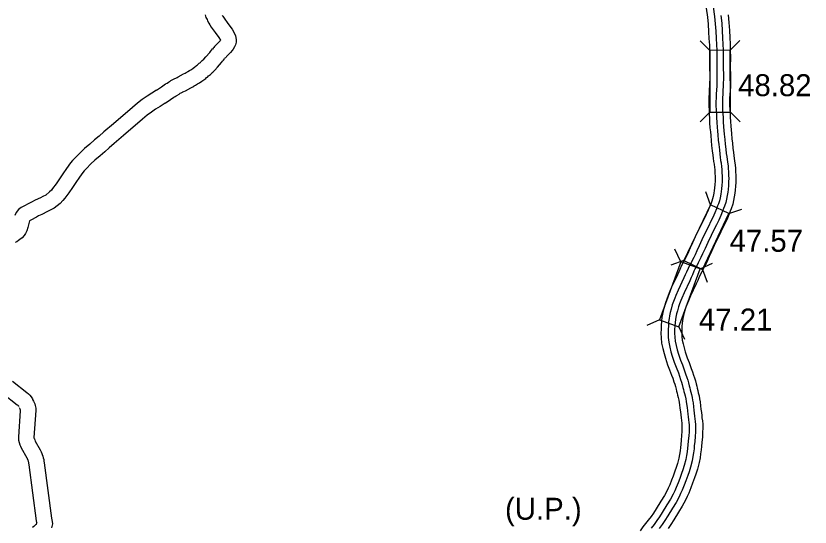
# Model space of a CAD drawing. Extents: x -939622 to -934245, y 1383184 to 1385301.
# Drawn here: x -936375.77 to -936329.92, y 1384824.91 to 1384854.42 of the extents above; entities that cross this region are included whole.
import ezdxf

# ---------------------------------------------------------------- set-up
doc = ezdxf.new("R2010")
doc.units = 0
for name, color, linetype in [('10', 7, 'Continuous'), ('19', 7, 'Continuous'), ('20', 7, 'Continuous'), ('25', 7, 'Continuous')]:
    doc.layers.add(name, color=color, linetype=linetype)

msp = doc.modelspace()

# ---------------------------------------------------------------- linework, layer by layer
at = {"layer": '10'}
for points in [[(-936364.852, 1384854.487), (-936364.799, 1384854.332), (-936364.74, 1384854.21), (-936364.704, 1384854.138), (-936364.639, 1384854.004), (-936364.577, 1384853.909), (-936364.491, 1384853.775), (-936364.262, 1384853.461), (-936364.057, 1384853.166), (-936363.969, 1384853.014), (-936363.984, 1384852.989), (-936364, 1384852.966), (-936364.046, 1384852.913), (-936364.092, 1384852.863), (-936364.136, 1384852.822), (-936364.197, 1384852.762), (-936364.246, 1384852.712), (-936364.305, 1384852.654), (-936364.354, 1384852.595), (-936364.389, 1384852.557), (-936364.429, 1384852.506)], [(-936363.855, 1384854.449), (-936363.822, 1384854.399), (-936363.749, 1384854.285), (-936363.529, 1384853.983), (-936363.296, 1384853.649), (-936363.175, 1384853.439), (-936363.088, 1384853.272), (-936363.053, 1384853.064), (-936363.054, 1384852.908), (-936363.103, 1384852.753), (-936363.149, 1384852.635), (-936363.225, 1384852.504), (-936363.288, 1384852.414), (-936363.375, 1384852.312), (-936363.456, 1384852.225), (-936363.515, 1384852.171), (-936363.557, 1384852.13), (-936363.605, 1384852.079), (-936363.643, 1384852.042), (-936363.678, 1384852), (-936363.704, 1384851.973), (-936363.721, 1384851.951)], [(-936367.65, 1384850.138), (-936367.359, 1384850.327), (-936367.136, 1384850.494), (-936367.041, 1384850.545), (-936366.961, 1384850.6), (-936366.897, 1384850.626), (-936366.885, 1384850.634), (-936366.822, 1384850.684), (-936366.708, 1384850.751), (-936366.628, 1384850.788), (-936366.597, 1384850.804), (-936366.549, 1384850.834), (-936366.459, 1384850.873), (-936366.413, 1384850.897), (-936366.097, 1384851.071), (-936365.991, 1384851.122), (-936365.934, 1384851.156), (-936365.873, 1384851.186), (-936365.838, 1384851.213), (-936365.75, 1384851.262), (-936365.72, 1384851.282), (-936365.679, 1384851.31), (-936365.557, 1384851.392), (-936365.443, 1384851.475), (-936365.376, 1384851.519), (-936365.341, 1384851.552), (-936365.285, 1384851.593), (-936365.265, 1384851.611), (-936365.193, 1384851.682), (-936365.122, 1384851.737), (-936365.09, 1384851.765), (-936365.068, 1384851.785), (-936365.05, 1384851.803), (-936365.019, 1384851.838), (-936364.926, 1384851.926), (-936364.8, 1384852.061), (-936364.586, 1384852.314), (-936364.542, 1384852.366), (-936364.487, 1384852.436), (-936364.423, 1384852.513)], [(-936367.16, 1384849.383), (-936366.843, 1384849.589), (-936366.651, 1384849.733), (-936366.573, 1384849.774), (-936366.529, 1384849.804), (-936366.474, 1384849.827), (-936366.356, 1384849.905), (-936366.312, 1384849.94), (-936366.289, 1384849.953), (-936366.238, 1384849.977), (-936366.157, 1384850.017), (-936366.127, 1384850.036), (-936366.074, 1384850.059), (-936365.99, 1384850.102), (-936365.682, 1384850.272), (-936365.562, 1384850.33), (-936365.506, 1384850.364), (-936365.475, 1384850.379), (-936365.401, 1384850.414), (-936365.341, 1384850.46), (-936365.286, 1384850.49), (-936365.221, 1384850.532), (-936365.174, 1384850.565), (-936365.04, 1384850.654), (-936364.928, 1384850.736), (-936364.812, 1384850.813), (-936364.764, 1384850.859), (-936364.72, 1384850.892), (-936364.651, 1384850.953), (-936364.599, 1384851.004), (-936364.545, 1384851.046), (-936364.488, 1384851.097), (-936364.456, 1384851.125), (-936364.404, 1384851.175), (-936364.37, 1384851.212), (-936364.285, 1384851.294), (-936364.128, 1384851.462), (-936363.895, 1384851.737), (-936363.843, 1384851.799), (-936363.787, 1384851.869), (-936363.727, 1384851.944)], [(-936367.652, 1384850.136), (-936367.927, 1384849.956), (-936368.203, 1384849.788), (-936368.474, 1384849.596), (-936368.752, 1384849.385), (-936369.045, 1384849.138), (-936370.143, 1384848.198), (-936370.691, 1384847.736), (-936370.974, 1384847.486), (-936371.239, 1384847.257), (-936371.509, 1384847.02), (-936371.806, 1384846.758), (-936372.066, 1384846.524), (-936372.346, 1384846.236), (-936372.502, 1384846.071), (-936372.622, 1384845.929), (-936372.842, 1384845.62), (-936373.057, 1384845.307), (-936373.255, 1384845.019), (-936373.455, 1384844.73), (-936373.652, 1384844.451), (-936373.724, 1384844.367), (-936373.829, 1384844.259), (-936374.054, 1384844.081), (-936374.216, 1384843.997), (-936374.354, 1384843.925), (-936374.661, 1384843.775), (-936374.878, 1384843.676), (-936375.029, 1384843.59), (-936375.32, 1384843.431), (-936375.476, 1384843.357), (-936375.624, 1384843.243), (-936375.764, 1384843.071), (-936375.828, 1384842.904)], [(-936367.158, 1384849.384), (-936367.446, 1384849.195), (-936367.709, 1384849.035), (-936367.941, 1384848.871), (-936368.189, 1384848.682), (-936368.462, 1384848.452), (-936369.56, 1384847.512), (-936370.103, 1384847.055), (-936370.381, 1384846.809), (-936370.647, 1384846.579), (-936370.914, 1384846.345), (-936371.207, 1384846.087), (-936371.442, 1384845.875), (-936371.697, 1384845.613), (-936371.83, 1384845.472), (-936371.909, 1384845.378), (-936372.104, 1384845.104), (-936372.316, 1384844.797), (-936372.514, 1384844.508), (-936372.718, 1384844.214), (-936372.941, 1384843.897), (-936373.058, 1384843.762), (-936373.223, 1384843.59), (-936373.565, 1384843.32), (-936373.801, 1384843.199), (-936373.948, 1384843.122), (-936374.276, 1384842.961), (-936374.469, 1384842.873), (-936374.591, 1384842.804), (-936374.911, 1384842.629), (-936374.98, 1384842.596), (-936375.092, 1384842.198), (-936375.145, 1384842.012), (-936375.21, 1384841.856), (-936375.304, 1384841.736), (-936375.418, 1384841.604), (-936375.544, 1384841.504), (-936375.63, 1384841.448), (-936375.723, 1384841.385), (-936375.824, 1384841.342)], [(-936375.975, 1384833.337), (-936375.145, 1384832.682), (-936375.037, 1384832.601), (-936374.97, 1384832.52), (-936374.901, 1384832.44), (-936374.823, 1384832.313), (-936374.785, 1384832.222)], [(-936376.534, 1384832.632), (-936375.695, 1384831.97), (-936375.664, 1384831.946), (-936375.657, 1384831.938), (-936375.629, 1384831.906), (-936375.626, 1384831.902), (-936375.615, 1384831.874)], [(-936374.811, 1384832.274), (-936374.755, 1384832.178), (-936374.688, 1384832.025), (-936374.663, 1384831.924), (-936374.64, 1384831.853), (-936374.63, 1384831.772), (-936374.626, 1384831.726), (-936374.614, 1384831.641), (-936374.728, 1384830.082), (-936374.729, 1384830.058), (-936374.727, 1384830.052), (-936374.707, 1384829.987), (-936374.686, 1384829.942), (-936374.658, 1384829.873), (-936374.378, 1384829.377), (-936374.305, 1384829.265), (-936374.273, 1384829.159), (-936374.249, 1384829.096), (-936374.217, 1384829.007), (-936374.19, 1384828.916), (-936374.166, 1384828.804), (-936374.153, 1384828.71), (-936374.143, 1384828.626), (-936373.711, 1384825.436), (-936373.689, 1384825.34), (-936373.673, 1384825.236), (-936373.664, 1384825.096), (-936373.697, 1384824.942), (-936373.717, 1384824.868)], [(-936375.589, 1384831.822), (-936375.558, 1384831.77), (-936375.544, 1384831.737), (-936375.53, 1384831.677), (-936375.523, 1384831.658), (-936375.521, 1384831.63), (-936375.519, 1384831.613), (-936375.628, 1384830.12), (-936375.63, 1384829.927), (-936375.588, 1384829.79), (-936375.55, 1384829.664), (-936375.509, 1384829.578), (-936375.469, 1384829.48), (-936375.149, 1384828.912), (-936375.13, 1384828.882), (-936375.124, 1384828.863), (-936375.092, 1384828.782), (-936375.073, 1384828.727), (-936375.063, 1384828.693), (-936375.054, 1384828.65), (-936375.046, 1384828.594), (-936375.035, 1384828.51), (-936374.597, 1384825.275), (-936374.574, 1384825.174), (-936374.571, 1384825.156), (-936374.58, 1384825.125), (-936374.602, 1384825.089), (-936374.612, 1384825.068), (-936374.634, 1384825.045), (-936374.683, 1384824.997), (-936374.747, 1384824.942), (-936374.811, 1384824.89)]]:
    msp.add_lwpolyline(points, dxfattribs=at)
at = {"layer": '19'}
for points in [[(-936335.93, 1384854.87), (-936335.848, 1384854.337), (-936335.807, 1384853.933), (-936335.781, 1384853.509), (-936335.759, 1384853.113), (-936335.738, 1384852.735), (-936335.728, 1384852.442)], [(-936335.523, 1384854.935), (-936335.438, 1384854.39), (-936335.396, 1384853.967), (-936335.369, 1384853.533), (-936335.347, 1384853.136), (-936335.326, 1384852.754), (-936335.315, 1384852.45)], [(-936335.066, 1384854.437), (-936335.022, 1384853.997), (-936334.995, 1384853.555), (-936334.972, 1384853.156), (-936334.952, 1384852.771), (-936334.94, 1384852.458)], [(-936334.657, 1384854.489), (-936334.611, 1384854.03), (-936334.583, 1384853.579), (-936334.561, 1384853.179), (-936334.54, 1384852.789), (-936334.528, 1384852.466)], [(-936335.728, 1384852.442), (-936335.726, 1384851.993), (-936335.727, 1384851.518), (-936335.718, 1384850.92), (-936335.725, 1384850.412), (-936335.744, 1384850.137), (-936335.751, 1384849.954), (-936335.765, 1384849.713), (-936335.773, 1384849.471), (-936335.772, 1384849.213), (-936335.758, 1384848.971), (-936335.742, 1384848.716), (-936335.734, 1384848.532), (-936335.724, 1384848.252), (-936335.701, 1384847.954), (-936335.677, 1384847.726), (-936335.658, 1384847.523), (-936335.631, 1384847.212), (-936335.605, 1384846.944), (-936335.571, 1384846.64), (-936335.541, 1384846.389), (-936335.52, 1384846.205), (-936335.493, 1384846.014), (-936335.469, 1384845.867), (-936335.44, 1384845.663), (-936335.431, 1384845.548), (-936335.42, 1384845.37), (-936335.41, 1384845.124), (-936335.404, 1384845.054), (-936335.411, 1384844.871), (-936335.425, 1384844.685), (-936335.442, 1384844.469), (-936335.456, 1384844.348), (-936335.482, 1384844.192), (-936335.518, 1384843.998), (-936335.548, 1384843.859), (-936335.59, 1384843.727), (-936335.643, 1384843.615), (-936335.707, 1384843.445), (-936335.806, 1384843.21), (-936335.916, 1384842.95), (-936336.035, 1384842.711), (-936336.145, 1384842.488), (-936336.346, 1384842.085), (-936336.549, 1384841.667), (-936336.704, 1384841.319), (-936336.843, 1384841.022), (-936336.941, 1384840.805), (-936337.009, 1384840.658), (-936337.078, 1384840.521), (-936337.161, 1384840.366), (-936337.252, 1384840.192), (-936337.342, 1384840.006), (-936337.436, 1384839.79), (-936337.503, 1384839.641), (-936337.584, 1384839.466), (-936337.914, 1384838.759), (-936338.052, 1384838.438), (-936338.116, 1384838.279), (-936338.196, 1384838.075), (-936338.271, 1384837.86), (-936338.346, 1384837.596), (-936338.395, 1384837.398), (-936338.44, 1384837.195), (-936338.473, 1384837.02), (-936338.503, 1384836.803), (-936338.517, 1384836.551), (-936338.528, 1384836.338), (-936338.532, 1384836.109), (-936338.524, 1384835.831), (-936338.494, 1384835.526), (-936338.428, 1384835.214), (-936338.355, 1384834.923), (-936338.268, 1384834.658), (-936338.148, 1384834.284), (-936338.031, 1384833.991), (-936337.914, 1384833.673), (-936337.855, 1384833.5), (-936337.787, 1384833.295), (-936337.738, 1384833.155), (-936337.7, 1384833.031), (-936337.659, 1384832.875), (-936337.631, 1384832.761), (-936337.604, 1384832.648), (-936337.576, 1384832.53), (-936337.546, 1384832.392), (-936337.509, 1384832.232), (-936337.483, 1384832.096), (-936337.46, 1384831.962), (-936337.437, 1384831.768), (-936337.413, 1384831.569), (-936337.392, 1384831.388), (-936337.372, 1384831.22), (-936337.353, 1384831.061), (-936337.333, 1384830.912), (-936337.323, 1384830.791), (-936337.321, 1384830.626), (-936337.325, 1384830.431), (-936337.337, 1384830.207), (-936337.369, 1384829.931), (-936337.391, 1384829.68)], [(-936335.315, 1384852.45), (-936335.313, 1384851.994), (-936335.314, 1384851.521), (-936335.305, 1384850.92), (-936335.313, 1384850.395), (-936335.332, 1384850.115), (-936335.339, 1384849.934), (-936335.353, 1384849.695), (-936335.36, 1384849.466), (-936335.359, 1384849.225), (-936335.346, 1384848.995), (-936335.33, 1384848.738), (-936335.322, 1384848.548), (-936335.312, 1384848.275), (-936335.29, 1384847.991), (-936335.267, 1384847.767), (-936335.247, 1384847.561), (-936335.22, 1384847.249), (-936335.195, 1384846.987), (-936335.161, 1384846.687), (-936335.132, 1384846.437), (-936335.11, 1384846.258), (-936335.086, 1384846.076), (-936335.062, 1384845.93), (-936335.03, 1384845.71), (-936335.019, 1384845.577), (-936335.008, 1384845.391), (-936334.998, 1384845.151), (-936334.991, 1384845.063), (-936334.999, 1384844.847), (-936335.014, 1384844.653), (-936335.032, 1384844.429), (-936335.047, 1384844.291), (-936335.076, 1384844.121), (-936335.113, 1384843.917), (-936335.149, 1384843.752), (-936335.205, 1384843.576), (-936335.263, 1384843.454), (-936335.324, 1384843.292), (-936335.426, 1384843.05), (-936335.54, 1384842.777), (-936335.665, 1384842.528), (-936335.775, 1384842.305), (-936335.976, 1384841.902), (-936336.175, 1384841.492), (-936336.329, 1384841.148), (-936336.468, 1384840.85), (-936336.566, 1384840.633), (-936336.637, 1384840.479), (-936336.712, 1384840.33), (-936336.797, 1384840.173), (-936336.884, 1384840.007), (-936336.967, 1384839.834), (-936337.059, 1384839.624), (-936337.128, 1384839.469), (-936337.21, 1384839.291), (-936337.538, 1384838.59), (-936337.671, 1384838.279), (-936337.733, 1384838.126), (-936337.809, 1384837.932), (-936337.878, 1384837.735), (-936337.948, 1384837.49), (-936337.993, 1384837.304), (-936338.036, 1384837.113), (-936338.066, 1384836.954), (-936338.092, 1384836.763), (-936338.106, 1384836.53), (-936338.116, 1384836.324), (-936338.12, 1384836.111), (-936338.112, 1384835.858), (-936338.086, 1384835.589), (-936338.026, 1384835.307), (-936337.958, 1384835.037), (-936337.876, 1384834.785), (-936337.76, 1384834.423), (-936337.646, 1384834.139), (-936337.525, 1384833.811), (-936337.464, 1384833.631), (-936337.396, 1384833.428), (-936337.346, 1384833.284), (-936337.303, 1384833.144), (-936337.26, 1384832.977), (-936337.23, 1384832.859), (-936337.203, 1384832.744), (-936337.173, 1384832.621), (-936337.144, 1384832.482), (-936337.105, 1384832.317), (-936337.078, 1384832.169), (-936337.052, 1384832.022), (-936337.028, 1384831.817), (-936337.003, 1384831.618), (-936336.982, 1384831.436), (-936336.962, 1384831.268), (-936336.944, 1384831.112), (-936336.923, 1384830.957), (-936336.911, 1384830.811), (-936336.909, 1384830.624), (-936336.912, 1384830.416), (-936336.926, 1384830.172), (-936336.958, 1384829.89), (-936336.98, 1384829.642)], [(-936334.94, 1384852.458), (-936334.938, 1384851.994), (-936334.939, 1384851.524), (-936334.93, 1384850.92), (-936334.938, 1384850.379), (-936334.958, 1384850.095), (-936334.965, 1384849.916), (-936334.979, 1384849.678), (-936334.985, 1384849.461), (-936334.984, 1384849.237), (-936334.972, 1384849.017), (-936334.955, 1384848.757), (-936334.947, 1384848.563), (-936334.937, 1384848.296), (-936334.917, 1384848.024), (-936334.894, 1384847.805), (-936334.874, 1384847.595), (-936334.847, 1384847.284), (-936334.822, 1384847.025), (-936334.789, 1384846.729), (-936334.759, 1384846.482), (-936334.738, 1384846.305), (-936334.715, 1384846.131), (-936334.691, 1384845.987), (-936334.658, 1384845.752), (-936334.645, 1384845.604), (-936334.634, 1384845.409), (-936334.624, 1384845.176), (-936334.615, 1384845.072), (-936334.625, 1384844.826), (-936334.64, 1384844.624), (-936334.659, 1384844.393), (-936334.676, 1384844.239), (-936334.706, 1384844.056), (-936334.745, 1384843.843), (-936334.787, 1384843.655), (-936334.855, 1384843.438), (-936334.917, 1384843.307), (-936334.976, 1384843.153), (-936335.08, 1384842.905), (-936335.199, 1384842.621), (-936335.329, 1384842.361), (-936335.439, 1384842.138), (-936335.639, 1384841.737), (-936335.835, 1384841.334), (-936335.988, 1384840.992), (-936336.127, 1384840.694), (-936336.225, 1384840.477), (-936336.3, 1384840.315), (-936336.38, 1384840.157), (-936336.465, 1384839.998), (-936336.549, 1384839.839), (-936336.626, 1384839.677), (-936336.716, 1384839.472), (-936336.787, 1384839.314), (-936336.871, 1384839.133), (-936337.195, 1384838.437), (-936337.325, 1384838.135), (-936337.385, 1384837.987), (-936337.457, 1384837.802), (-936337.52, 1384837.622), (-936337.585, 1384837.393), (-936337.628, 1384837.218), (-936337.669, 1384837.037), (-936337.696, 1384836.893), (-936337.719, 1384836.727), (-936337.731, 1384836.51), (-936337.741, 1384836.311), (-936337.744, 1384836.113), (-936337.738, 1384835.882), (-936337.714, 1384835.647), (-936337.661, 1384835.391), (-936337.598, 1384835.141), (-936337.519, 1384834.9), (-936337.407, 1384834.55), (-936337.296, 1384834.274), (-936337.172, 1384833.936), (-936337.109, 1384833.751), (-936337.041, 1384833.549), (-936336.99, 1384833.4), (-936336.943, 1384833.247), (-936336.896, 1384833.07), (-936336.866, 1384832.948), (-936336.838, 1384832.831), (-936336.808, 1384832.703), (-936336.778, 1384832.564), (-936336.738, 1384832.394), (-936336.709, 1384832.236), (-936336.68, 1384832.076), (-936336.655, 1384831.862), (-936336.631, 1384831.662), (-936336.609, 1384831.479), (-936336.59, 1384831.312), (-936336.572, 1384831.159), (-936336.55, 1384830.998), (-936336.536, 1384830.829), (-936336.534, 1384830.623), (-936336.538, 1384830.403), (-936336.552, 1384830.14), (-936336.585, 1384829.852), (-936336.606, 1384829.608)], [(-936334.528, 1384852.466), (-936334.526, 1384851.995), (-936334.527, 1384851.526), (-936334.517, 1384850.92), (-936334.526, 1384850.361), (-936334.546, 1384850.072), (-936334.553, 1384849.896), (-936334.566, 1384849.66), (-936334.573, 1384849.455), (-936334.572, 1384849.249), (-936334.56, 1384849.042), (-936334.544, 1384848.778), (-936334.535, 1384848.579), (-936334.525, 1384848.32), (-936334.506, 1384848.061), (-936334.483, 1384847.846), (-936334.463, 1384847.633), (-936334.436, 1384847.321), (-936334.411, 1384847.068), (-936334.379, 1384846.776), (-936334.35, 1384846.531), (-936334.329, 1384846.358), (-936334.307, 1384846.193), (-936334.283, 1384846.049), (-936334.248, 1384845.798), (-936334.233, 1384845.633), (-936334.222, 1384845.43), (-936334.212, 1384845.202), (-936334.202, 1384845.082), (-936334.213, 1384844.803), (-936334.228, 1384844.593), (-936334.248, 1384844.353), (-936334.267, 1384844.182), (-936334.3, 1384843.985), (-936334.341, 1384843.761), (-936334.388, 1384843.549), (-936334.47, 1384843.287), (-936334.537, 1384843.146), (-936334.592, 1384843), (-936334.7, 1384842.745), (-936334.824, 1384842.448), (-936334.96, 1384842.178), (-936335.07, 1384841.955), (-936335.269, 1384841.555), (-936335.461, 1384841.16), (-936335.613, 1384840.821), (-936335.752, 1384840.522), (-936335.85, 1384840.306), (-936335.928, 1384840.136), (-936336.014, 1384839.966), (-936336.101, 1384839.804), (-936336.18, 1384839.654), (-936336.251, 1384839.505), (-936336.338, 1384839.305), (-936336.411, 1384839.142), (-936336.497, 1384838.959), (-936336.819, 1384838.269), (-936336.944, 1384837.976), (-936337.002, 1384837.834), (-936337.07, 1384837.659), (-936337.126, 1384837.498), (-936337.187, 1384837.287), (-936337.227, 1384837.124), (-936337.264, 1384836.955), (-936337.288, 1384836.827), (-936337.308, 1384836.686), (-936337.319, 1384836.489), (-936337.328, 1384836.297), (-936337.332, 1384836.115), (-936337.326, 1384835.908), (-936337.306, 1384835.71), (-936337.259, 1384835.484), (-936337.201, 1384835.255), (-936337.127, 1384835.027), (-936337.018, 1384834.69), (-936336.911, 1384834.422), (-936336.783, 1384834.074), (-936336.718, 1384833.883), (-936336.651, 1384833.682), (-936336.598, 1384833.528), (-936336.546, 1384833.36), (-936336.497, 1384833.172), (-936336.465, 1384833.046), (-936336.437, 1384832.927), (-936336.405, 1384832.794), (-936336.375, 1384832.654), (-936336.334, 1384832.479), (-936336.303, 1384832.31), (-936336.272, 1384832.135), (-936336.246, 1384831.911), (-936336.221, 1384831.712), (-936336.2, 1384831.527), (-936336.18, 1384831.36), (-936336.163, 1384831.21), (-936336.14, 1384831.042), (-936336.124, 1384830.849), (-936336.121, 1384830.621), (-936336.125, 1384830.388), (-936336.141, 1384830.105), (-936336.175, 1384829.811), (-936336.196, 1384829.57)], [(-936337.391, 1384829.68), (-936337.407, 1384829.508), (-936337.431, 1384829.315), (-936337.463, 1384829.11), (-936337.498, 1384828.899), (-936337.581, 1384828.588), (-936337.656, 1384828.356), (-936337.728, 1384828.149), (-936337.832, 1384827.85), (-936337.916, 1384827.624), (-936338.029, 1384827.36), (-936338.117, 1384827.168), (-936338.193, 1384826.993), (-936338.335, 1384826.726), (-936338.538, 1384826.417), (-936338.804, 1384825.975), (-936338.965, 1384825.725), (-936339.103, 1384825.522), (-936339.261, 1384825.309), (-936339.416, 1384825.114), (-936339.569, 1384824.922), (-936339.738, 1384824.703)], [(-936336.98, 1384829.642), (-936336.997, 1384829.463), (-936337.023, 1384829.258), (-936337.056, 1384829.044), (-936337.095, 1384828.812), (-936337.185, 1384828.471), (-936337.265, 1384828.224), (-936337.338, 1384828.014), (-936337.444, 1384827.71), (-936337.533, 1384827.471), (-936337.651, 1384827.193), (-936337.74, 1384827), (-936337.821, 1384826.814), (-936337.98, 1384826.516), (-936338.189, 1384826.197), (-936338.453, 1384825.757), (-936338.621, 1384825.497), (-936338.767, 1384825.283), (-936338.933, 1384825.058), (-936339.094, 1384824.857)], [(-936336.606, 1384829.608), (-936336.624, 1384829.421), (-936336.651, 1384829.206), (-936336.685, 1384828.984), (-936336.728, 1384828.733), (-936336.825, 1384828.365), (-936336.91, 1384828.104), (-936336.984, 1384827.891), (-936337.091, 1384827.583), (-936337.185, 1384827.332), (-936337.308, 1384827.042), (-936337.398, 1384826.847), (-936337.483, 1384826.651), (-936337.656, 1384826.325), (-936337.871, 1384825.998), (-936338.135, 1384825.558), (-936338.309, 1384825.29), (-936338.461, 1384825.066), (-936338.636, 1384824.83)], [(-936336.196, 1384829.57), (-936336.214, 1384829.376), (-936336.243, 1384829.149), (-936336.278, 1384828.919), (-936336.324, 1384828.646), (-936336.429, 1384828.249), (-936336.519, 1384827.973), (-936336.595, 1384827.755), (-936336.703, 1384827.444), (-936336.802, 1384827.179), (-936336.931, 1384826.875), (-936337.021, 1384826.678), (-936337.112, 1384826.471), (-936337.301, 1384826.114), (-936337.522, 1384825.778), (-936337.785, 1384825.34), (-936337.965, 1384825.062), (-936338.124, 1384824.828)]]:
    msp.add_lwpolyline(points, dxfattribs=at)
at = {"layer": '20'}
for p, q in [((-936335.715, 1384852.431), (-936336.277, 1384852.989)), ((-936334.527, 1384852.436), (-936333.969, 1384852.998)), ((-936335.702, 1384848.867), (-936336.26, 1384848.305)), ((-936334.514, 1384848.872), (-936333.952, 1384848.314)), ((-936335.68, 1384843.517), (-936335.946, 1384844.263)), ((-936334.607, 1384843.008), (-936333.861, 1384843.273)), ((-936337.393, 1384840.228), (-936337.725, 1384840.947)), ((-936337.208, 1384840.297), (-936337.954, 1384840.031)), ((-936336.278, 1384839.818), (-936335.559, 1384840.15)), ((-936336.135, 1384839.788), (-936335.869, 1384839.042)), ((-936338.624, 1384836.883), (-936339.342, 1384836.551)), ((-936337.509, 1384836.473), (-936337.176, 1384835.754))]:
    msp.add_line(p, q, dxfattribs=at)
for points in [[(-936334.514, 1384848.872), (-936334.527, 1384852.436), (-936335.715, 1384852.431), (-936335.702, 1384848.867)], [(-936335.68, 1384843.517), (-936337.208, 1384840.297), (-936336.135, 1384839.788), (-936334.607, 1384843.008)], [(-936337.509, 1384836.473), (-936336.278, 1384839.818), (-936337.393, 1384840.228), (-936338.624, 1384836.883)]]:
    msp.add_lwpolyline(points, close=True, dxfattribs=at)

# ---------------------------------------------------------------- texts
at = {"layer": '25'}
for s, p in [('48.82', (-936334.076, 1384849.786)), ('47.57', (-936334.572, 1384840.804)), ('47.21', (-936336.338, 1384836.258)), ('(U.P.)', (-936347.534, 1384825.336))]:
    msp.add_text(s, height=1.2672, dxfattribs=at).set_placement(p)

doc.saveas('drawing.dxf')
